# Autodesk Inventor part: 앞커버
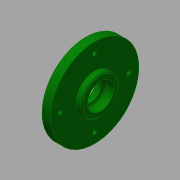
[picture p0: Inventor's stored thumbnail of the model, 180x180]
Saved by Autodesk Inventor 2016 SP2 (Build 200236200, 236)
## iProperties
Created: 2015-09
Part Number: 앞커버
Material: 알루미늄 6061
Document SubType Name: Modeling
Designer: mduedu
Density: 2.71 g/cm^3
Mass: 58.9874 g
Surface Area: 98.7754 cm^2
Volume: 21.7666 cm^3
Appearance: 진녹색
Author: mduedu
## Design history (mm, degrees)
sketch "스케치1"
  geometry: L1 (-6.5, 63)-(-11.5, 63); L2 (-11.5, 63)-(-11.5, 84.5); L3 (-11.5, 84.5)-(-19.5, 84.5); L4 (-19.5, 84.5)-(-19.5, 70.5); L5 (-24.5, 70.5)-(-24.5, 54.5); L6 (-24.5, 54.5)-(-6.5, 54.5); L7 (-6.5, 54.5)-(-6.5, 63); L8 (-79.5, 39.5)-(-79.5, 54.5) reference; L9 (48.5, 54.5)-(48.5, 39.5) reference; L10 (-79.5, 47)-(48.5, 47); L11 (-19.5, 70.5)-(-24.5, 70.5); 3 further points
  constraints: 18 end point, 6 parallel, 4 midpoint, 1 horizontal, 1 perpendicular, 1 vertical alignment
  dimensions: "d0" = 18 distance between parallel lines of L7 L5; "d3" = 32 diameter of L1 L10; "d5" = 5 distance of L1.start L1.end; "d6" = 75 diameter of L3 L10; "d7" = 8 distance of L2.end L3.end; "d8" = 47 diameter of L4.end L10; "d61" = 15 diameter of L6 L10
revolve "회전1" sketch "스케치1" stored, may be unused: angle "d4" = 90 deg
sketch "스케치2"
  geometry: C1 r 37.5 at (0, 0) reference; 2 further points
  constraints: 1 coincident
hole "구멍1" sketch "스케치2" at (0, 0) diameter "d11" = 22; stored, may be unused: countersink angle "d15" = 90 deg, drill point angle "d17" = 0 deg; dims "d12" = 6, "d13" = 4, "d14" = 2, "d16" = 8
fillet "모깎기1" dims "d18" = 3
fillet "모깎기2" dims "d19" = 1
sketch "스케치3"
  geometry: C1 r 37.5 at (0, 0) reference; 2 further points
  constraints: 1 coincident
hole "구멍2" sketch "스케치3" at (0, 0) diameter "d20" = 30; stored, may be unused: countersink angle "d24" = 90 deg, drill point angle "d26" = 0 deg; dims "d21" = 6, "d22" = 4, "d23" = 2, "d25" = 7.5
fillet "모깎기3" dims "d27" = 0.3
chamfer "모따기1" distance "d28" = 1; stored, may be unused: second distance "d29" = 2, angle "d30" = 30 deg
sketch "스케치7" dims "d56" = 58
  geometry: C1 r 37.5 at (0, 0) reference; 5 further points
  constraints: 2 vertical alignment, 1 coincident, 7 other
  dimensions: "d59" = 360 deg dimension on C1.centre point (0, 29) (derived)
hole "구멍4" sketch "스케치7" at (0, 29), (-29, 0), (0, -29), (29, 0) diameter "d48" = 3.4; stored, may be unused: countersink angle "d52" = 90 deg, drill point angle "d54" = 0 deg; dims "d49" = 6, "d50" = 6.5, "d51" = 3.4, "d53" = 8
hole "구멍5" diameter "d64" = 17; stored, may be unused: countersink angle "d68" = 90 deg, drill point angle "d70" = 118 deg; dims "d62" = 10, "d63" = 10, "d65" = 6, "d66" = 4, "d67" = 2, "d69" = 8
chamfer "모따기2" distance "d71" = 1; stored, may be unused: second distance "d72" = 2, angle "d73" = 45 deg
node "솔리드1"
node "참조1"
node "참조2"
